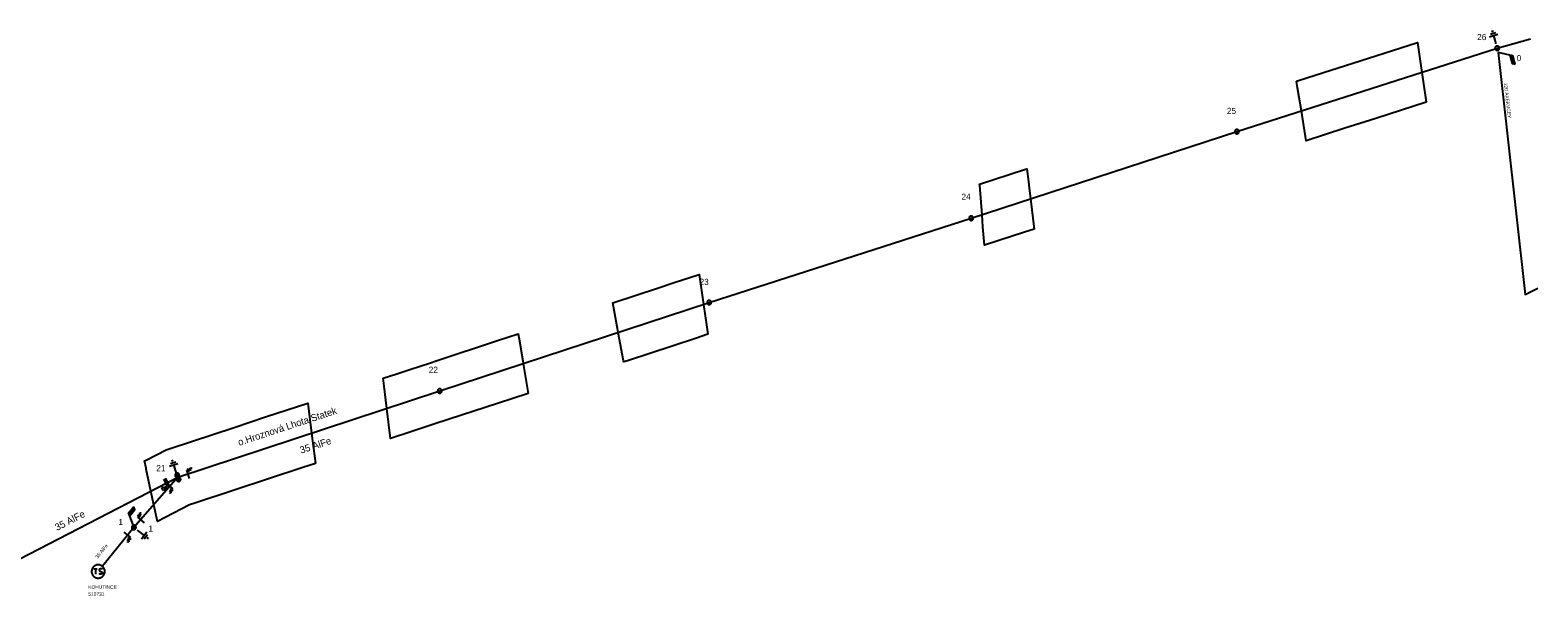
# Model space of a CAD drawing. Extents: x -544790 to -541580, y -1198998 to -1195432.
# Drawn here: x -542020.6 to -541591.3, y -1198704.5 to -1198543.3 of the extents above; entities that cross this region are included whole.
import ezdxf

# ---------------------------------------------------------------- set-up
doc = ezdxf.new("R2010")
doc.units = 0
for name, color, linetype in [('DOPLŇ_POPISY', 7, 'Continuous'), ('ELE_EON_POPIS', 7, 'Continuous'), ('Implicitní', 7, 'Continuous'), ('KN_HRAN_K_Ú', 7, 'Continuous'), ('KN_HRAN_KRAJSKÁ', 7, 'Continuous'), ('KN_HRAN_POHYBLIVÁ', 7, 'Continuous'), ('KN_PARC_Č', 7, 'Continuous'), ('KONEC_VEDENÍ', 7, 'Continuous'), ('PB_NN', 7, 'Continuous'), ('PB_NN_POPIS', 7, 'Continuous'), ('PK_HRAN_SPORNÁ', 7, 'Continuous'), ('PLG_EXPORT_GPE', 7, 'Continuous'), ('PODZEM_NN_POPIS', 7, 'Continuous'), ('PROJEKT', 7, 'Continuous'), ('RÁMEČEK', 7, 'Continuous'), ('SDEL_EON_POPIS', 7, 'Continuous'), ('SR', 7, 'Continuous'), ('TECH_OCHR_PÁSMO_HRAN', 7, 'Continuous'), ('ZRUŠENO', 7, 'Continuous')]:
    doc.layers.add(name, color=color, linetype=linetype)

# ---------------------------------------------------------------- blocks, each defined once
blk = doc.blocks.new('VN850')
at = {"layer": 'RÁMEČEK'}
for points in [[(-0.56, 1.43), (-0.56, -1.07)], [(-0.01, 1.43), (-0.01, -1.07)], [(-2.09, -0.54), (-1.78, -0.54)], [(-2.09, -1.41), (-2.09, -0.54)], [(-1.78, -1.41), (-2.09, -1.41)], [(-1.78, -0.54), (-1.66, -0.6)], [(-1.67, -1.35), (-1.78, -1.41)], [(-1.59, -1.2), (-1.67, -1.35)], [(-1.66, -0.6), (-1.59, -0.75)], [(-1.59, -0.75), (-1.55, -0.96)], [(-1.55, -0.96), (-1.59, -1.2)], [(-1.26, -0.54), (-1.26, -1.41)], [(-0.85, -0.54), (-1.26, -1.09)], [(-1.13, -0.92), (-0.77, -1.41)]]:
    blk.add_lwpolyline(points, dxfattribs=at)
blk = doc.blocks.new('VN840')
at = {"layer": 'RÁMEČEK'}
for points in [[(-0.01, 1.41), (-0.01, -1.09)], [(-1.51, -1.24), (-1.51, -1.15)], [(-1.48, -1.35), (-1.51, -1.24)], [(-1.33, -1.42), (-1.48, -1.35)], [(-1.27, -1.42), (-1.33, -1.42)], [(-1.13, -1.35), (-1.27, -1.42)], [(-1.09, -1.24), (-1.13, -1.35)], [(-1.09, -0.59), (-1.09, -1.24)], [(-0.68, -0.59), (-0.68, -1.42)], [(-0.68, -1.11), (-0.27, -0.59)], [(-0.54, -0.94), (-0.2, -1.42)]]:
    blk.add_lwpolyline(points, dxfattribs=at)
blk = doc.blocks.new('VN440')
at = {"layer": 'ELE_EON_POPIS'}
for points in [[(1.22, 0), (1.21, 0.13), (1.19, 0.25), (1.16, 0.38), (1.11, 0.5), (1.05, 0.61), (0.98, 0.72), (0.9, 0.82), (0.81, 0.91), (0.71, 0.99), (0.6, 1.06), (0.49, 1.12), (0.37, 1.16), (0.25, 1.2), (0.12, 1.22), (-0.01, 1.22), (-0.14, 1.22), (-0.26, 1.2), (-0.39, 1.16), (-0.51, 1.12), (-0.62, 1.06), (-0.73, 0.99), (-0.83, 0.91), (-0.92, 0.82), (-1, 0.72), (-1.07, 0.61), (-1.13, 0.5), (-1.18, 0.38), (-1.21, 0.25), (-1.23, 0.13), (-1.24, 0), (-1.23, -0.13), (-1.21, -0.26), (-1.18, -0.38), (-1.13, -0.5), (-1.07, -0.62), (-1, -0.73), (-0.92, -0.83), (-0.83, -0.92), (-0.73, -1), (-0.62, -1.07), (-0.51, -1.13), (-0.39, -1.17), (-0.26, -1.2), (-0.14, -1.23), (-0.01, -1.23), (0.12, -1.23), (0.25, -1.2), (0.37, -1.17), (0.49, -1.13), (0.6, -1.07), (0.71, -1), (0.81, -0.92), (0.9, -0.83), (0.98, -0.73), (1.05, -0.62), (1.11, -0.5), (1.16, -0.38), (1.19, -0.26), (1.21, -0.13), (1.22, 0)], [(-1.24, 0), (1.22, 0)], [(-1.18, -0.34), (1.1, -0.34)], [(-1.01, -0.63), (0.97, -0.63)], [(-0.74, -0.92), (0.68, -0.92)]]:
    blk.add_lwpolyline(points, dxfattribs=at)
blk = doc.blocks.new('VN810')
at = {"layer": 'PLG_EXPORT_GPE'}
for points in [[(1.25, -3.75), (-1.25, -3.75)], [(0, -1.25), (0, -3.75)], [(0.77, -4.37), (-0.8, -4.37)], [(0, -5), (-0.25, -5)], [(0.27, -5), (0, -5)]]:
    blk.add_lwpolyline(points, dxfattribs=at)
blk = doc.blocks.new('VN610')
at = {"layer": 'ZRUŠENO'}
for points in [[(1.88, 0), (1.87, 0.2), (1.84, 0.39), (1.79, 0.58), (1.72, 0.77), (1.63, 0.94), (1.52, 1.11), (1.4, 1.26), (1.26, 1.4), (1.1, 1.53), (0.94, 1.63), (0.76, 1.72), (0.58, 1.8), (0.39, 1.85), (0.19, 1.88), (-0.01, 1.89), (-0.21, 1.88), (-0.4, 1.85), (-0.59, 1.8), (-0.78, 1.72), (-0.95, 1.63), (-1.12, 1.53), (-1.27, 1.4), (-1.41, 1.26), (-1.54, 1.11), (-1.64, 0.94), (-1.73, 0.77), (-1.8, 0.58), (-1.86, 0.39), (-1.89, 0.2), (-1.9, 0), (-1.89, -0.2), (-1.86, -0.39), (-1.8, -0.58), (-1.73, -0.77), (-1.64, -0.95), (-1.54, -1.11), (-1.41, -1.27), (-1.27, -1.41), (-1.12, -1.53), (-0.95, -1.64), (-0.78, -1.73), (-0.59, -1.8), (-0.4, -1.85), (-0.21, -1.88), (-0.01, -1.89), (0.19, -1.88), (0.39, -1.85), (0.58, -1.8), (0.76, -1.73), (0.94, -1.64), (1.1, -1.53), (1.26, -1.41), (1.4, -1.27), (1.52, -1.11), (1.63, -0.95), (1.72, -0.77), (1.79, -0.58), (1.84, -0.39), (1.87, -0.2), (1.88, 0)], [(-1.27, 0.78), (-0.26, 0.78)], [(-0.76, 0.78), (-0.76, -0.79)], [(1.19, 0.66), (0.94, 0.78), (0.62, 0.78), (0.37, 0.66), (0.24, 0.47), (0.24, 0.4), (0.37, 0.22), (1.12, -0.16), (1.25, -0.32), (1.25, -0.48), (1.12, -0.67), (0.87, -0.79), (0.62, -0.79), (0.49, -0.73), (0.24, -0.6)]]:
    blk.add_lwpolyline(points, dxfattribs=at)
blk = doc.blocks.new('VN450')
at = {"layer": 'ELE_EON_POPIS'}
for points in [[(0, 0), (-0.01, 0.13), (-0.03, 0.25), (-0.06, 0.38), (-0.11, 0.5), (-0.16, 0.61), (-0.23, 0.72), (-0.31, 0.82), (-0.4, 0.91), (-0.5, 0.99), (-0.61, 1.06), (-0.72, 1.11), (-0.84, 1.16), (-0.97, 1.19), (-1.09, 1.21), (-1.22, 1.22), (-1.35, 1.21), (-1.47, 1.19), (-1.59, 1.16), (-1.71, 1.11), (-1.83, 1.06), (-1.93, 0.99), (-2.03, 0.91), (-2.12, 0.82), (-2.2, 0.72), (-2.27, 0.61), (-2.33, 0.5), (-2.38, 0.38), (-2.41, 0.25), (-2.43, 0.13), (-2.44, 0), (-2.43, -0.13), (-2.41, -0.25), (-2.38, -0.38), (-2.33, -0.5), (-2.27, -0.61), (-2.2, -0.72), (-2.12, -0.82), (-2.03, -0.91), (-1.93, -0.99), (-1.83, -1.06), (-1.71, -1.11), (-1.59, -1.16), (-1.47, -1.19), (-1.35, -1.21), (-1.22, -1.22), (-1.09, -1.21), (-0.97, -1.19), (-0.84, -1.16), (-0.72, -1.11), (-0.61, -1.06), (-0.5, -0.99), (-0.4, -0.91), (-0.31, -0.82), (-0.23, -0.72), (-0.16, -0.61), (-0.11, -0.5), (-0.06, -0.38), (-0.03, -0.25), (-0.01, -0.13), (0, 0)], [(-2.44, 0), (2.44, 0)], [(2.44, 0), (2.43, 0.13), (2.41, 0.25), (2.38, 0.38), (2.33, 0.5), (2.27, 0.61), (2.2, 0.72), (2.12, 0.82), (2.03, 0.91), (1.94, 0.99), (1.83, 1.06), (1.71, 1.11), (1.6, 1.16), (1.47, 1.19), (1.35, 1.21), (1.22, 1.22), (1.09, 1.21), (0.97, 1.19), (0.84, 1.16), (0.72, 1.11), (0.61, 1.06), (0.5, 0.99), (0.4, 0.91), (0.31, 0.82), (0.23, 0.72), (0.16, 0.61), (0.11, 0.5), (0.06, 0.38), (0.03, 0.25), (0.01, 0.13), (0, 0), (0.01, -0.13), (0.03, -0.25), (0.06, -0.38), (0.11, -0.5), (0.16, -0.61), (0.23, -0.72), (0.31, -0.82), (0.4, -0.91), (0.5, -0.99), (0.61, -1.06), (0.72, -1.11), (0.84, -1.16), (0.97, -1.19), (1.09, -1.21), (1.22, -1.22), (1.35, -1.21), (1.47, -1.19), (1.6, -1.16), (1.71, -1.11), (1.83, -1.06), (1.94, -0.99), (2.03, -0.91), (2.12, -0.82), (2.2, -0.72), (2.27, -0.61), (2.33, -0.5), (2.38, -0.38), (2.41, -0.25), (2.43, -0.13), (2.44, 0)], [(-2.4, -0.31), (-0.04, -0.31)], [(-2.26, -0.61), (-0.17, -0.61)], [(-2.01, -0.92), (-0.42, -0.92)], [(0.04, -0.31), (2.4, -0.31)], [(0.17, -0.61), (2.27, -0.61)], [(0.42, -0.92), (2.02, -0.92)]]:
    blk.add_lwpolyline(points, dxfattribs=at)
blk = doc.blocks.new('VN001')
at = {"layer": 'Implicitní'}
for p, q in [((1.73, 3.03), (4.14, 3.03)), ((1.76, 3.08), (4.17, 3.08)), ((1.79, 3.13), (4.2, 3.13)), ((1.82, 3.18), (4.23, 3.18)), ((1.85, 3.23), (4.26, 3.23)), ((1.87, 3.28), (4.29, 3.28)), ((1.9, 3.33), (4.32, 3.33)), ((1.93, 3.38), (4.35, 3.38)), ((1.96, 3.43), (4.37, 3.43)), ((1.99, 3.48), (4.4, 3.48)), ((2.02, 3.53), (4.43, 3.53)), ((2.05, 3.58), (4.46, 3.58)), ((2.07, 3.63), (4.49, 3.63)), ((2.1, 3.68), (4.52, 3.68)), ((2.13, 3.73), (2.54, 3.73))]:
    blk.add_line(p, q, dxfattribs=at)
blk.add_lwpolyline([(2.13, 3.73), (0, 0)], dxfattribs=at)
blk.add_lwpolyline([(4.55, 3.73), (2.13, 3.73), (1.7, 2.98), (4.12, 2.99)], close=True, dxfattribs=at)

msp = doc.modelspace()

# ---------------------------------------------------------------- linework, layer by layer
at = {"layer": 'PK_HRAN_SPORNÁ'}
for points in [[(-541660.03, -1198557.82), (-541656.79, -1198556.79), (-541637.5, -1198550.6), (-541625.6, -1198546.78), (-541625.12, -1198550.12), (-541624.38, -1198555.31), (-541623.35, -1198562.5), (-541623.16, -1198563.85), (-541637.5, -1198568.45), (-541646.26, -1198571.26), (-541657.27, -1198574.79), (-541658.65, -1198566.31), (-541659.27, -1198562.5), (-541659.72, -1198559.72)], [(-541734.77, -1198599.98), (-541737.5, -1198600.87), (-541748.88, -1198604.59), (-541749.3, -1198599.3), (-541749.57, -1198595.87), (-541750.22, -1198587.5), (-541750.25, -1198587.15), (-541737.5, -1198582.99), (-541736.81, -1198582.77), (-541736.38, -1198586.38), (-541736.25, -1198587.5), (-541735.79, -1198591.38)], [(-541831.12, -1198631.12), (-541837.5, -1198633.22), (-541850.52, -1198637.5), (-541851.58, -1198637.85), (-541851.64, -1198637.5), (-541853.12, -1198629.41), (-541853.33, -1198628.33), (-541854.67, -1198620.97), (-541841.71, -1198616.71), (-541837.5, -1198615.33), (-541830.08, -1198612.89), (-541828.85, -1198621.43), (-541827.92, -1198627.92), (-541827.62, -1198629.97)], [(-541878.79, -1198646.79), (-541887.5, -1198649.65), (-541901.3, -1198654.19), (-541905.61, -1198655.61), (-541912.5, -1198657.89), (-541917.93, -1198659.68), (-541918.97, -1198651.07), (-541919.74, -1198644.74), (-541920.01, -1198642.46), (-541916.21, -1198641.21), (-541912.5, -1198639.99), (-541906.62, -1198638.05), (-541904.95, -1198637.5), (-541887.5, -1198631.76), (-541881.6, -1198629.82), (-541881.35, -1198631.35), (-541880.32, -1198637.5), (-541880.19, -1198638.31)], [(-541939.35, -1198666.74), (-541942.92, -1198667.92), (-541962.5, -1198674.38), (-541973.64, -1198678.06), (-541975.2, -1198678.57), (-541982.15, -1198682.15), (-541984.34, -1198683.28), (-541985.35, -1198678.53), (-541986.17, -1198674.67), (-541987.5, -1198668.43), (-541987.56, -1198668.15), (-541988, -1198666.05), (-541987.5, -1198665.79), (-541981.8, -1198662.85), (-541980.74, -1198662.5), (-541962.5, -1198656.48), (-541953.52, -1198653.52), (-541941.5, -1198649.55), (-541940.42, -1198658.15), (-541939.88, -1198662.5), (-541939.61, -1198664.61)]]:
    msp.add_lwpolyline(points, close=True, dxfattribs=at)
at = {"layer": 'PODZEM_NN_POPIS'}
for points in [[(-541978.5, -1198670.71), (-541903.96, -1198646.12), (-541827.24, -1198620.9), (-541752.66, -1198596.88), (-541677.01, -1198572.2), (-541602.9, -1198548.42)], [(-541602.9, -1198548.42), (-541593.41, -1198545.78)], [(-542035.15, -1198699.92), (-541978.5, -1198670.71)]]:
    msp.add_lwpolyline(points, dxfattribs=at)
at = {"layer": 'PROJEKT'}
msp.add_lwpolyline([(-541602.68, -1198549.62), (-541594.95, -1198618.59), (-541591.34, -1198616.84)], dxfattribs=at)
at = {"layer": 'SDEL_EON_POPIS'}
for points in [[(-541978.5, -1198670.71), (-541991.02, -1198684.99)], [(-541991.02, -1198684.99), (-541999.97, -1198696.07)]]:
    msp.add_lwpolyline(points, dxfattribs=at)

# ---------------------------------------------------------------- block references
at = {"layer": 'DOPLŇ_POPISY'}
for name, p, xscale, yscale, rotation in [('VN440', (-541602.9, -1198548.42), 0.5, 0.5, 15.67416104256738), ('VN440', (-541677.01, -1198572.2), 0.49999999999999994, 0.5000000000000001, 15.674363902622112), ('VN440', (-541752.66, -1198596.88), 0.5, 0.5000000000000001, 15.67480842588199), ('VN440', (-541827.24, -1198620.9), 0.5000000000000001, 0.5000000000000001, 18.196858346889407), ('VN440', (-541903.96, -1198646.12), 0.5, 0.5, 18.25726940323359), ('VN450', (-541978.5, -1198670.71), 0.5, 0.5, -71.25863055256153), ('VN440', (-541991.02, -1198684.99), 0.5, 0.5, 51.05784991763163)]:
    msp.add_blockref(name, p, dxfattribs=dict(at, xscale=xscale, yscale=yscale, rotation=rotation))
at = {"layer": 'KN_HRAN_KRAJSKÁ', "rotation": 0.005377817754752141}
msp.add_blockref('VN610', (-542001.17, -1198697.55), dxfattribs=at)
at = {"layer": 'KN_HRAN_POHYBLIVÁ'}
for name, p, rotation in [('VN840', (-541975.62, -1198669.76), -161.74172498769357), ('VN850', (-541981.47, -1198672.24), 27.2767082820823), ('VN840', (-541980.75, -1198673.28), 48.75706946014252), ('VN840', (-541989.11, -1198682.81), -131.24268615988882), ('VN840', (-541992.81, -1198687.21), 51.05680560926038)]:
    msp.add_blockref(name, p, dxfattribs=dict(at, rotation=rotation))
at = {"layer": 'RÁMEČEK'}
for p, rotation in [((-541602.9, -1198548.42), -164.43349457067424), ((-541978.5, -1198670.71), -161.757594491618), ((-541991.02, -1198684.99), 51.05749730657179)]:
    msp.add_blockref('VN810', p, dxfattribs=dict(at, rotation=rotation))
at = {"layer": 'TECH_OCHR_PÁSMO_HRAN'}
for p, rotation in [((-541602.68, -1198549.62), -73.91033892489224), ((-541991.02, -1198684.99), 51.055269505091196)]:
    msp.add_blockref('VN001', p, dxfattribs=dict(at, rotation=rotation))

# ---------------------------------------------------------------- texts
at = {"layer": 'KN_HRAN_K_Ú'}
msp.add_text('510731', height=1, rotation=0.005, dxfattribs=at).set_placement((-542004, -1198704.5))
at = {"layer": 'KN_PARC_Č'}
msp.add_text('KOHUTINCE', height=1, rotation=0.005, dxfattribs=at).set_placement((-542004, -1198702.5))
at = {"layer": 'KONEC_VEDENÍ'}
for s, p in [('0', (-541597.39, -1198552.11)), ('1', (-541986.89, -1198686.21))]:
    msp.add_text(s, height=1.75, dxfattribs=at).set_placement(p)
at = {"layer": 'PB_NN'}
for rotation, p in [(18.257, (-541943.39, -1198664.01)), (27.277, (-542012.9, -1198686.04))]:
    msp.add_text('35 AlFe', height=2, rotation=rotation, dxfattribs=at).set_placement(p)
at = {"layer": 'PB_NN_POPIS'}
msp.add_text('o.Hroznová Lhota Statek', height=2, rotation=18.257, dxfattribs=at).set_placement((-541961.03, -1198661.77))
at = {"layer": 'PLG_EXPORT_GPE'}
for s, p in [('26', (-541608.62, -1198546.12)), ('25', (-541679.86, -1198567.17)), ('24', (-541755.42, -1198591.63)), ('23', (-541829.98, -1198615.89)), ('22', (-541907.07, -1198640.96)), ('21', (-541984.64, -1198668.99)), ('1', (-541995.43, -1198684.35))]:
    msp.add_text(s, height=1.75, dxfattribs=at).set_placement(p)
at = {"layer": 'SR'}
msp.add_text('35 AlFe', height=1, rotation=51.057, dxfattribs=at).set_placement((-542001.33, -1198693.95))
at = {"layer": 'ZRUŠENO'}
msp.add_text('120 AXEKVCEY', height=1, rotation=276.394, dxfattribs=at).set_placement((-541601.03, -1198558.37))

doc.saveas('drawing.dxf')
